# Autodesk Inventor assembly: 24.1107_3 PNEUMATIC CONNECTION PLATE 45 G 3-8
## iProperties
Created: 2007-06
Part Number: 24.1107_3 PNEUMATIC CONNECTION PLATE 45 G 3-8
Document SubType Name: Assembly
Designer: Andy Moles
Author: Andy Moles
